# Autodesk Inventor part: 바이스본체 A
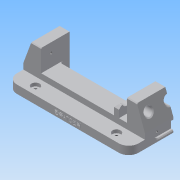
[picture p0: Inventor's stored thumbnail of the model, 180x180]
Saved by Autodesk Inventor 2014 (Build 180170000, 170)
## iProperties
Created: 2017-04
Part Number: 바이스본체 A
Material: 알루미늄 6061
Document SubType Name: Modeling
Designer: mduedu
Density: 2.71 g/cm^3
Mass: 324.199 g
Surface Area: 276.734 cm^2
Volume: 119.631 cm^3
Appearance: 기본값
Author: mduedu
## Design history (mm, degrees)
sketch "스케치1"
  geometry: L1 (-75, 0)-(75, 0); L2 (-75, 0)-(-75, 17); L3 (-53, 17)-(53, 17); L4 (75, 17)-(75, 0); L5 (-75, 17)-(-65.173, 44); L6 (-65.173, 44)-(-53, 44); L7 (-53, 44)-(-53, 17); L8 (0, 0)-(0, 17); L9 (75, 17)-(65.173, 44); L10 (65.173, 44)-(53, 44); L11 (53, 44)-(53, 17); 1 further point
  constraints: 22 end point, 4 perpendicular, 2 horizontal alignment, 2 midpoint, 2 symmetric about line, 1 coincident, 1 collinear, 1 horizontal, 1 vertical
  dimensions: "d0" = 150 distance of L1.start L1.end; "d1" = 17 distance of L1.start L2.end; "d2" = 27 distance of L3.start L6.end; "d3" = 22 distance of L3.start L2.end; "d4" = 70 deg angle of L3 L5; "d54" = 20 deg angle of L9 L4
extrude "돌출1" new body sketch "스케치1" stored distance "d5" = 70; taper "d6" = 0 deg
sketch "스케치2"
  geometry: L1 (0, 70)-(106, 70) reference; L2 (106, 70)-(106, 0) reference; L3 (106, 0)-(0, 0) reference; L4 (0, 47)-(106, 47); L5 (106, 47)-(106, 23); L6 (106, 23)-(0, 23); L7 (0, 23)-(0, 47); L8 (0, 70)-(0, 0) reference; 2 further points
  constraints: 8 end point, 2 parallel, 2 point on line, 1 horizontal, 1 horizontal alignment, 1 midpoint, 1 perpendicular
  dimensions: "d7" = 24 distance between parallel lines of L6 L4
extrude "돌출2" cut sketch "스케치2" stored distance "d9" = 70; taper "d10" = 0 deg
sketch "스케치3"
  geometry: L1 (22, -23)-(128, -23) reference; L2 (128, -47)-(22, -47) reference; L3 (22, -18)-(128, -18); L4 (128, -52)-(22, -52); L5 (22, -18)-(22, -52); L6 (128, -18)-(128, -52); 1 further point
  constraints: 8 end point, 3 parallel, 2 point on line, 1 perpendicular
  dimensions: "d11" = 5 distance between parallel lines of L3 L1; "d12" = 5 distance between parallel lines of L4 L2
extrude "돌출3" cut sketch "스케치3" distance "d13" = 12; taper "d14" = 0 deg
fillet "모깎기1" dims "d15" = 3, "d16" = 3
sketch "스케치4"
  geometry: L1 (103, 23)-(3, 23) reference; L2 (0, 26)-(0, 0) reference; L3 (106, 0)-(0, 0) reference; L4 (106, 26)-(106, 0) reference; L5 (96, 0)-(90, 0); L6 (90, 0)-(90, 19.5); L7 (96, 19.5)-(96, 0); L8 (90, 19.5)-(96, 19.5); A1 r 3 centre (3, 26) between (0, 26) and (3, 23) reference; A2 r 3 centre (103, 26) between (103, 23) and (106, 26) reference; 1 further point
  constraints: 8 end point, 2 perpendicular, 1 horizontal, 1 parallel, 1 point on line
  dimensions: "d17" = 10 distance between parallel lines of L7 L4; "d18" = 6 distance between parallel lines of L7 L6; "d27" = 3.5 distance between parallel lines of L8 L1
extrude "돌출4" join sketch "스케치4" distance "d19" = 12; taper "d20" = 0 deg
chamfer "모따기1" distance "d21" = 3; stored, may be unused: second distance "d22" = 2, angle "d23" = 45 deg
chamfer "모따기2" distance "d24" = 3; stored, may be unused: second distance "d25" = 2, angle "d26" = 45 deg
sketch "스케치5"
  geometry: L1 (-15.5, 35.8)-(-15.5, -25.8) reference; L2 (19.5, 0)-(0, 0) reference; C1 r 6.5 at (9.5, 15); 1 further point
  constraints: 1 centre point
  dimensions: "d28" = 13 diameter of C1; "d30" = 15 distance from line of C1.centre L2; "d31" = 25 distance from line of C1.centre L1
extrude "돌출5" cut sketch "스케치5" stored distance "d32" = 12; taper "d33" = 0 deg
sketch "스케치6"
  geometry: C1 r 5 at (-10, 15); C2 r 5 at (-60, 15); A1 r 6.5 centre (-10, 15) between (-15.766, 12) and (-4.234, 12) reference; A2 r 6.5 centre (-60, 15) between (-65.766, 12) and (-54.234, 12) reference; 1 further point
  constraints: 2 centre point, 2 coincident
  dimensions: "d34" = 10 diameter of C1; "d35" = 10 diameter of C2 (= d34)
extrude "돌출6" cut sketch "스케치6" stored distance "d36" = 12; taper "d37" = 0 deg
chamfer "모따기3" distance "d38" = 1; stored, may be unused: second distance "d39" = 2, angle "d40" = 45 deg
chamfer "모따기4" distance "d41" = 1; stored, may be unused: second distance "d42" = 2, angle "d43" = 45 deg
sketch "스케치7"
  geometry: L1 (-35, 35.8)-(-35, -25.8) reference; L2 (-70, 0)-(0, 0) reference; C1 r 5 at (-35, 15); 1 further point
  constraints: 1 centre point, 1 point on line
  dimensions: "d44" = 10 diameter of C1; "d45" = 15 distance from line of C1.centre L2
extrude "돌출7" cut sketch "스케치7" stored distance "d46" = 12; taper "d47" = 0 deg
chamfer "모따기5" distance "d48" = 1; stored, may be unused: second distance "d49" = 2, angle "d50" = 45 deg
node "작업축1"
sketch "스케치8"
  geometry: L1 (-105, 32)-(105, 32) reference; L2 (58, 32)-(64, 32); L3 (64, 32)-(64, 40); L4 (64, 40)-(58, 40); L5 (58, 40)-(58, 32); L6 (53, 38)-(53, 26) reference; 1 further point
  constraints: 8 end point, 2 parallel, 1 horizontal, 1 perpendicular, 1 point on line
  dimensions: "d51" = 5 distance from line of L6 L2.start; "d52" = 6 distance of L3.end L4.end; "d53" = 16 diameter of L4 L1
revolve "회전1" sketch "스케치8" stored, may be unused: angle "d55" = 90 deg
fillet "모깎기2"
chamfer "모따기6" distance "d56" = 1; stored, may be unused: second distance "d57" = 2, angle "d58" = 45 deg
sketch "스케치9"
  geometry: L1 (17.5, 3)-(52.5, 3); L2 (52.5, 13)-(17.5, 13); L3 (70, 0)-(0, 0) reference; L4 (17.5, 8)-(52.5, 8); A1 r 5 centre (17.5, 8) between (17.5, 13) and (17.5, 3); A2 r 5 centre (52.5, 8) between (52.5, 3) and (52.5, 13); 3 further points
  constraints: 6 end point, 4 point on circle, 3 tangent, 2 centre point, 2 midpoint, 2 parallel, 1 horizontal, 1 vertical alignment
  dimensions: "d59" = 35 distance of L4.start L4.end; "d61" = 5 radius of A2; "d62" = 8 distance between parallel lines of L3 L4
extrude "돌출8" cut sketch "스케치9" distance "d63" = 3; taper "d64" = 0 deg
chamfer "모따기7" distance "d65" = 1; stored, may be unused: second distance "d66" = 2, angle "d67" = 45 deg
chamfer "모따기8" distance "d68" = 1; stored, may be unused: second distance "d69" = 2, angle "d70" = 45 deg
feature "분할1"
sketch "스케치10"
  geometry: L1 (35, 27)-(0, 27) reference; L2 (0, 0)-(0, 27) reference; 1 further point
  dimensions: "d85" = 11.5 distance from line of point (12, 15.5) L1; "d86" = 12 distance from line of point (12, 15.5) L2
hole "구멍1" sketch "스케치10" at (12, 15.5) diameter "d71" = 3.242; stored, may be unused: countersink angle "d75" = 90 deg, drill point angle "d77" = 120 deg; dims "d72" = 6, "d73" = 4, "d74" = 2, "d76" = 8
sketch "스케치11"
  geometry: A1 r 5 centre (17.5, 8) between (17.5, 13) and (17.5, 3) reference; 1 further point
  constraints: 1 coincident
hole "구멍3" sketch "스케치11" at (17.5, 8) diameter "d78" = 2.459; stored, may be unused: countersink angle "d82" = 90 deg, drill point angle "d84" = 120 deg; dims "d79" = 4.5, "d80" = 4, "d81" = 2, "d83" = 6
sketch "스케치13"
  geometry: L1 (75, 0)-(75, 35) reference; L2 (-75, 0)-(-75, 35) reference; L3 (-75, 35)-(75, 35); L4 (75, 35)-(75, 55); L5 (75, 55)-(-75, 55); L6 (-75, 55)-(-75, 35); 1 further point
  constraints: 8 end point, 2 parallel, 1 horizontal, 1 perpendicular, 1 point on line
  dimensions: "d90" = 20 distance between parallel lines of L5 L3; "d94" = 150 distance of L4.end L5.end (derived)
extrude "돌출9" join sketch "스케치13" distance "d92" = 10; taper "d93" = 0 deg
sketch "스케치14"
  geometry: L1 (-75, -35)-(-75, -55) reference; L2 (75, -55)-(75, -35) reference; L3 (-75, -45)-(75, -45); 3 further points
  constraints: 2 end point, 2 midpoint, 2 point on line
  dimensions: "d95" = 50 horizontal distance of point (-50, -45) point (0, 0); "d96" = 100 distance of point (50, -45) point (-50, -45)
fillet "모깎기3" dims "d97" = 12
chamfer "모따기9" distance "d98" = 1; stored, may be unused: second distance "d99" = 2, angle "d100" = 45 deg
hole "구멍4" sketch "스케치14" diameter "d101" = 4.134; stored, may be unused: countersink angle "d105" = 90 deg, drill point angle "d107" = 118 deg; dims "d102" = 6, "d103" = 10, "d104" = 4, "d106" = 8
sketch "스케치15"
  geometry: L1 (0, 0)-(126, 0) reference; 3 further points
  constraints: 1 midpoint, 1 vertical alignment, 1 other
  dimensions: "d109" = 5 distance from line of point (63, 5) L1
feature "엠보싱2" sketch "스케치15" dims "d0" = 150, "d1" = 17, "d2" = 27, "d3" = 22, "d4" = 70 deg, "d54" = 20 deg, "d110" = 0.5, "d111" = 0
node "솔리드1"
mirror "대칭1"
mirror "대칭2"
mirror "대칭3"
mirror "대칭4"
node "투영된 루프1"
